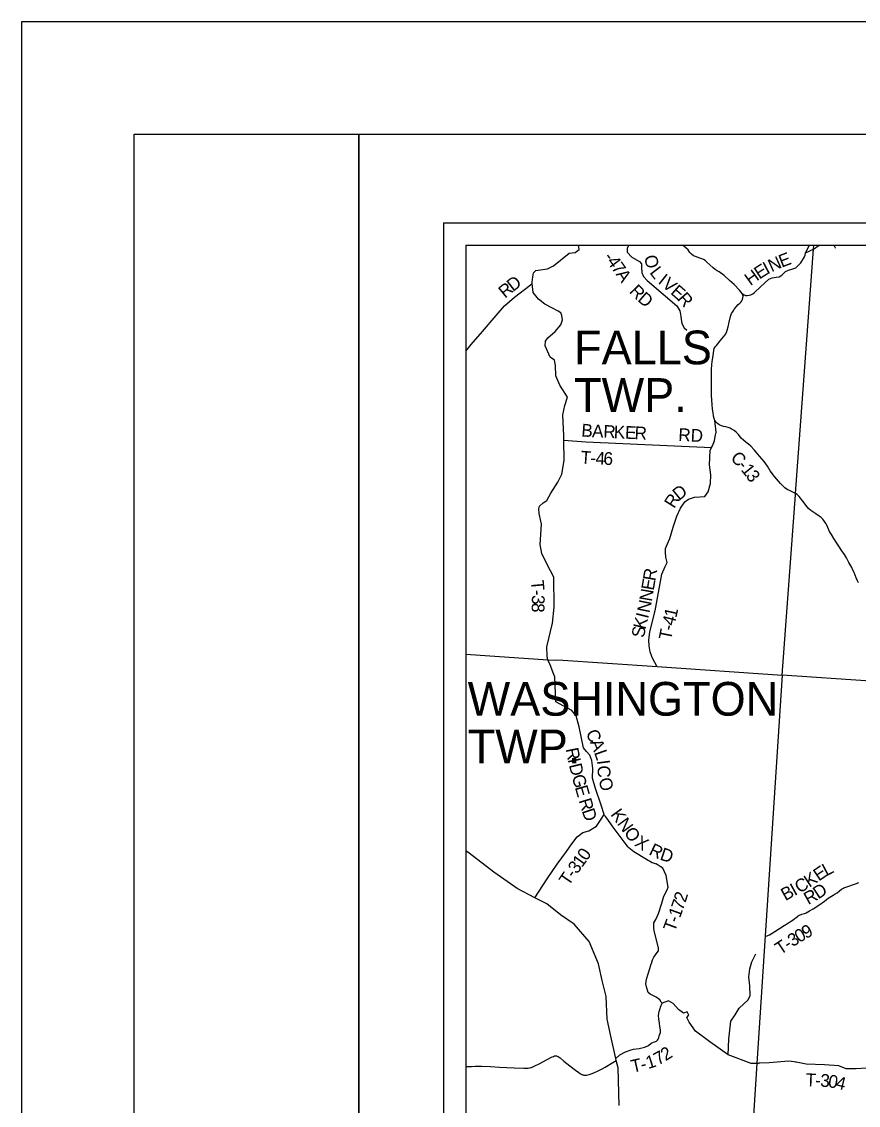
# Model space of a CAD drawing. Extents: x 0 to 34, y 0 to 22.
# Drawn here: x 0 to 3.722, y 17.181 to 22 of the extents above; entities that cross this region are included whole.
import ezdxf

# ---------------------------------------------------------------- set-up
doc = ezdxf.new("R2010")
doc.units = 0
for name, color, linetype in [('GM_X_County_Road', 7, 'Continuous'), ('GM_X_County_Road_Text', 7, 'Continuous'), ('GM_X_Township_Road', 7, 'Continuous'), ('GM_X_Township_Road_Text', 7, 'Continuous'), ('GM_X_Township_Text', 7, 'Continuous'), ('SH_Border', 7, 'Continuous'), ('SH_Cut_Line', 7, 'Continuous'), ('SH_Data', 7, 'Continuous')]:
    doc.layers.add(name, color=color, linetype=linetype)

msp = doc.modelspace()

# ---------------------------------------------------------------- linework, layer by layer
at = {"layer": 'GM_X_County_Road'}
for points in [[(3.2063, 20.7907), (3.1935, 20.8065), (3.1705, 20.8311), (3.1499, 20.8493), (3.1254, 20.8705), (3.1031, 20.888), (3.0945, 20.8927), (3.0849, 20.8984), (3.076, 20.9052), (3.0619, 20.9182), (3.0488, 20.9307), (3.0403, 20.938), (3.0331, 20.9423), (3.0256, 20.9455), (3.0172, 20.9485), (2.9974, 20.9551), (2.9897, 20.959), (2.9808, 20.9661), (2.9733, 20.974), (2.9646, 20.9848), (2.9552, 20.9937), (2.9394, 21.0054)], [(3.0837, 20.2266), (3.0811, 20.2354), (3.0786, 20.2456), (3.0761, 20.2607), (3.0739, 20.2773), (3.0716, 20.2977), (3.0702, 20.3174), (3.0696, 20.3385), (3.0697, 20.3687), (3.0692, 20.4145), (3.0697, 20.4539), (3.0708, 20.4738), (3.0727, 20.4885), (3.0753, 20.5045), (3.0776, 20.5253), (3.079, 20.5389), (3.0816, 20.5465), (3.0852, 20.5535), (3.0907, 20.5601), (3.1079, 20.58), (3.1294, 20.6079), (3.1355, 20.6175), (3.139, 20.628), (3.1428, 20.643), (3.1473, 20.6643), (3.1536, 20.689), (3.1587, 20.7021), (3.162, 20.7087), (3.168, 20.7171), (3.1721, 20.7232), (3.1885, 20.7422), (3.1952, 20.7479), (3.2008, 20.7544), (3.2041, 20.7592), (3.2075, 20.7649), (3.2089, 20.7718), (3.2094, 20.779), (3.2089, 20.7832), (3.2063, 20.7907)], [(3.443, 19.9019), (3.4342, 19.9066), (3.4164, 19.9144), (3.4089, 19.9184), (3.4019, 19.9226), (3.3959, 19.9273), (3.3888, 19.9336), (3.3765, 19.9467), (3.3667, 19.9571), (3.3499, 19.9776), (3.3308, 20.0033), (3.3177, 20.0234), (3.3029, 20.0445), (3.2833, 20.0679), (3.2675, 20.0858), (3.2593, 20.0963), (3.2438, 20.1123), (3.2342, 20.1212), (3.2239, 20.1285), (3.2122, 20.1385), (3.2014, 20.1484), (3.1887, 20.1636), (3.1784, 20.1748), (3.1702, 20.1818), (3.1615, 20.1871), (3.1524, 20.1922), (3.1437, 20.1946), (3.1329, 20.1975), (3.1226, 20.1999), (3.1137, 20.2027), (3.1069, 20.2054), (3.1018, 20.2081), (3.0957, 20.2128), (3.0915, 20.2168), (3.0837, 20.2266)], [(3.7237, 19.505), (3.719, 19.5135), (3.7135, 19.526), (3.7084, 19.5382), (3.7032, 19.5504), (3.6986, 19.5602), (3.6928, 19.5732), (3.6806, 19.595), (3.6695, 19.6155), (3.6606, 19.6301), (3.6497, 19.6471), (3.6138, 19.7011), (3.6023, 19.7187), (3.5941, 19.7334), (3.5873, 19.75), (3.5819, 19.7608), (3.5789, 19.7668), (3.5742, 19.7732), (3.5684, 19.7814), (3.5638, 19.7871), (3.5571, 19.7943), (3.5486, 19.8016), (3.5339, 19.8113), (3.5114, 19.8256), (3.5011, 19.8349), (3.4952, 19.8419), (3.4748, 19.8675), (3.4586, 19.8881), (3.4501, 19.8966), (3.443, 19.9019)], [(2.6581, 17.1799), (2.6533, 17.3472), (2.6457, 17.3805), (2.6437, 17.3894), (2.6215, 17.4892), (2.6049, 17.5635), (2.6005, 17.6656), (2.5832, 17.7362), (2.5659, 17.8105), (2.5254, 17.9102), (2.4576, 17.9863), (2.3967, 18.0286), (2.3362, 18.0777), (2.2832, 18.1036), (2.2047, 18.1459), (2.1001, 18.2173), (1.9913, 18.3019), (1.9763, 18.3122)], [(1.9763, 17.3536), (1.9803, 17.3536), (2.002, 17.354), (2.0175, 17.3548), (2.033, 17.3554), (2.0425, 17.3552), (2.0453, 17.3552), (2.0855, 17.3529), (2.1258, 17.3511), (2.191, 17.3475), (2.2344, 17.3458), (2.2469, 17.3458), (2.2532, 17.3464), (2.2594, 17.3473), (2.2655, 17.3488), (2.2685, 17.3498), (2.2743, 17.352), (2.28, 17.3547), (2.3049, 17.3675), (2.3352, 17.3834), (2.3599, 17.3963), (2.3656, 17.3987), (2.3713, 17.4005), (2.3742, 17.4009), (2.3771, 17.401), (2.38, 17.4006), (2.3828, 17.3998), (2.3855, 17.3986), (2.3907, 17.3954), (2.3956, 17.3916), (2.4124, 17.3778), (2.439, 17.3563), (2.4636, 17.3375), (2.4785, 17.3265), (2.4861, 17.3211), (2.4916, 17.3181), (2.4945, 17.3168), (2.4976, 17.3158), (2.5007, 17.3153), (2.5067, 17.3148), (2.5096, 17.3149), (2.5127, 17.3152), (2.5189, 17.3164), (2.5249, 17.318), (2.5338, 17.3211), (2.5453, 17.3259), (2.5652, 17.3349), (2.582, 17.3431), (2.5956, 17.3505), (2.6306, 17.3708), (2.6457, 17.3805)]]:
    msp.add_lwpolyline(points, dxfattribs=at)
at = {"layer": 'GM_X_Township_Road'}
for points in [[(1.9763, 20.5346), (2.0003, 20.5641), (2.0498, 20.6217), (2.1114, 20.6937), (2.1479, 20.7357), (2.1931, 20.7752), (2.2623, 20.8286), (2.271, 20.8361), (2.2714, 20.8415), (2.2737, 20.8646), (2.2772, 20.8824), (2.2882, 20.8934), (2.339, 20.9006), (2.366, 20.9138), (2.4363, 20.9699), (2.4625, 20.9736), (2.48, 20.9873), (2.4774, 21.0054)], [(2.7005, 21.0054), (2.7, 21.0049), (2.6939, 20.9909), (2.6946, 20.9753), (2.7147, 20.9521), (2.7488, 20.9339), (2.7575, 20.9225), (2.7579, 20.9164), (2.7578, 20.9062), (2.7589, 20.8853), (2.7661, 20.8671), (2.7835, 20.8489), (2.9153, 20.7357), (2.9285, 20.7137), (2.9308, 20.6993)], [(3.2063, 20.7907), (3.2138, 20.7846), (3.2211, 20.7828), (3.2279, 20.7821), (3.2361, 20.7834), (3.2439, 20.7851), (3.2532, 20.7898), (3.2603, 20.7949), (3.2864, 20.821), (3.3241, 20.8555), (3.3396, 20.8612), (3.3575, 20.8631), (3.37, 20.8657), (3.3825, 20.8733), (3.3981, 20.8888), (3.4118, 20.8952), (3.4315, 20.9005), (3.4448, 20.9058), (3.4661, 20.927), (3.4832, 20.954), (3.4863, 20.9623), (3.487, 20.9727), (3.5047, 21.0054)], [(3.487, 20.9727), (3.5229, 20.9876), (3.5477, 21.0054)], [(3.6148, 21.0024), (3.6172, 20.9981), (3.6191, 20.9931)], [(2.3679, 19.0967), (2.3508, 19.1396), (2.3414, 19.1616), (2.3385, 19.1788), (2.3371, 19.2202), (2.3613, 19.325), (2.3692, 19.3959), (2.3672, 19.5303), (2.338, 19.5856), (2.3141, 19.6353), (2.3072, 19.6744), (2.3133, 19.7658), (2.3026, 19.8125), (2.3003, 19.8338), (2.3034, 19.8448), (2.3204, 19.86), (2.336, 19.8702), (2.3546, 19.9037), (2.3849, 19.9515), (2.4027, 19.988), (2.413, 20.0487), (2.4126, 20.1382), (2.4125, 20.158), (2.4083, 20.2517), (2.4163, 20.2924), (2.4292, 20.3299), (2.3938, 20.3842), (2.3768, 20.4255), (2.3752, 20.4714), (2.3706, 20.4942), (2.3513, 20.5086), (2.3284, 20.5591), (2.3303, 20.5796), (2.3407, 20.5944), (2.3733, 20.6225), (2.3988, 20.6516), (2.406, 20.6738), (2.4035, 20.693), (2.3984, 20.7045), (2.3876, 20.7127), (2.3595, 20.7268), (2.3269, 20.7443), (2.2996, 20.7659), (2.2755, 20.7963), (2.271, 20.8361)], [(2.9308, 20.6993), (2.9326, 20.6879), (2.934, 20.6766), (2.9364, 20.6583), (2.9473, 20.6378), (2.9594, 20.6281)], [(2.8036, 19.1772), (2.7961, 19.1971), (2.7921, 19.2244), (2.7904, 19.2495), (2.795, 19.2859), (2.8189, 19.3793), (2.8477, 19.5423), (2.8637, 19.5777), (2.8646, 19.5796), (2.8713, 19.5946), (2.8665, 19.6182), (2.8648, 19.6403), (2.8652, 19.6573), (2.8729, 19.6777), (2.8833, 19.701), (2.8993, 19.7519), (2.9145, 19.8017), (2.9305, 19.837), (2.9501, 19.8643), (2.9675, 19.8768), (2.9942, 19.8849), (3.0395, 19.8888), (3.0544, 19.9086), (3.0644, 19.9467), (3.0668, 19.985), (3.0606, 20.0288), (3.0629, 20.0933), (3.0696, 20.1066), (3.0736, 20.1143), (3.0828, 20.1354), (3.0848, 20.1551), (3.09, 20.1739), (3.0837, 20.2266)], [(2.4126, 20.1382), (2.5098, 20.1315), (3.0696, 20.1066)], [(2.8278, 19.1316), (2.8064, 19.1698), (2.8036, 19.1772)], [(2.591, 18.4737), (2.5779, 18.5158), (2.5528, 18.5894), (2.5403, 18.6365), (2.5407, 18.6782), (2.5368, 18.7146), (2.5273, 18.7378), (2.5133, 18.7537), (2.5, 18.7704), (2.481, 18.8648), (2.4666, 18.913), (2.4476, 18.9361), (2.3762, 18.9755), (2.3747, 19.0127), (2.3719, 19.0867), (2.3679, 19.0967)], [(2.2832, 18.1036), (2.3382, 18.1876), (2.3829, 18.2541), (2.4239, 18.3092), (2.4482, 18.3445), (2.4709, 18.3753), (2.4965, 18.3935), (2.5232, 18.4012), (2.5578, 18.4225), (2.5752, 18.4494), (2.591, 18.4737), (2.5967, 18.4652)], [(2.5967, 18.4652), (2.6058, 18.4515), (2.6256, 18.4244), (2.6787, 18.3527), (2.6943, 18.3329), (2.7229, 18.3098), (2.7796, 18.2755), (2.8048, 18.2609), (2.8227, 18.2548)], [(2.8016, 17.8121), (2.8059, 17.8274), (2.812, 17.8396), (2.8275, 17.8601), (2.8332, 17.8681), (2.8336, 17.8806), (2.816, 17.9511), (2.8119, 17.9675), (2.8131, 17.9918), (2.8214, 18.0073), (2.8328, 18.0339), (2.8476, 18.0806), (2.8566, 18.1117), (2.8718, 18.1395), (2.876, 18.1505), (2.8669, 18.2032), (2.8525, 18.2355), (2.8407, 18.2433), (2.8227, 18.2548)], [(3.3142, 17.9331), (3.3229, 17.9371), (3.3268, 17.9392), (3.3511, 17.9544), (3.3717, 17.9673), (3.392, 17.9806), (3.411, 17.9931), (3.4248, 18.002), (3.4363, 18.0095), (3.4417, 18.0131), (3.4464, 18.0166), (3.4511, 18.0208), (3.4554, 18.0241), (3.4599, 18.0268), (3.4639, 18.0288), (3.4674, 18.0301), (3.4708, 18.0312), (3.4769, 18.0327), (3.4825, 18.0339), (3.4871, 18.0354), (3.4901, 18.0371), (3.5053, 18.0455), (3.5215, 18.0551), (3.5553, 18.077), (3.563, 18.0822), (3.5702, 18.0877), (3.5806, 18.0968), (3.5877, 18.102), (3.5957, 18.1068), (3.6106, 18.1157), (3.6198, 18.1208), (3.6281, 18.1266), (3.6383, 18.1346), (3.6471, 18.1416), (3.6527, 18.1454), (3.6582, 18.1481), (3.6668, 18.1511), (3.7136, 18.1681), (3.7209, 18.1709), (3.725, 18.1725)], [(3.1427, 17.4048), (3.1462, 17.4745), (3.155, 17.5555), (3.1738, 17.584), (3.192, 17.6128), (3.2323, 17.6495), (3.2419, 17.6698), (3.2398, 17.7119), (3.2347, 17.7519), (3.2394, 17.7873), (3.248, 17.8197), (3.266, 17.8553)], [(2.8312, 17.4747), (2.8341, 17.4814), (2.8356, 17.4905), (2.8425, 17.5049), (2.8428, 17.5163), (2.8394, 17.5311), (2.8371, 17.547), (2.8352, 17.5649), (2.8333, 17.5801), (2.836, 17.5979), (2.8402, 17.6112), (2.8424, 17.6176), (2.8501, 17.6346), (2.8455, 17.64), (2.8394, 17.6503), (2.8223, 17.6624), (2.8139, 17.6662), (2.8048, 17.6703), (2.7965, 17.6752), (2.787, 17.6828), (2.7794, 17.7082), (2.7771, 17.7215), (2.7798, 17.742), (2.7949, 17.7887), (2.801, 17.8101), (2.8016, 17.8121)], [(3.1427, 17.4048), (3.0613, 17.4636), (2.9975, 17.5106), (2.9692, 17.5503), (2.9591, 17.5722), (2.9677, 17.5826), (2.9615, 17.5968), (2.9443, 17.5911), (2.9227, 17.6075), (2.8983, 17.6339), (2.8777, 17.6454), (2.8501, 17.6346)], [(2.6437, 17.3894), (2.6611, 17.4052), (2.6858, 17.4182), (2.7115, 17.4272), (2.7214, 17.4307), (2.7476, 17.4334), (2.773, 17.4392), (2.789, 17.4468), (2.8004, 17.4578), (2.8117, 17.4624), (2.8239, 17.4666), (2.8292, 17.47), (2.8312, 17.4747)], [(3.2796, 17.3678), (3.2766, 17.3673), (3.2716, 17.3665), (3.2451, 17.3667), (3.1427, 17.4048)], [(3.4432, 17.3733), (3.4373, 17.3741), (3.4126, 17.3775), (3.3255, 17.3696), (3.2845, 17.3686), (3.2796, 17.3678)], [(3.7885, 17.3464), (3.7868, 17.346), (3.7855, 17.346), (3.7823, 17.346), (3.7637, 17.3459), (3.759, 17.3461), (3.7128, 17.3428), (3.668, 17.343), (3.6353, 17.357), (3.572, 17.3611), (3.4909, 17.3644), (3.4452, 17.373), (3.4432, 17.3733)]]:
    msp.add_lwpolyline(points, dxfattribs=at)
at = {"layer": 'GM_X_Township_Text'}
for points in [[(1.9763, 19.187), (2.3412, 19.1621), (2.3735, 19.1599), (2.3853, 19.1626), (2.8276, 19.1321), (3.3833, 19.0938), (3.4423, 19.896), (3.4428, 19.9024), (3.5227, 20.9882), (3.524, 21.0054)], [(8.7763, 18.7365), (7.7116, 18.8006), (7.6851, 18.802), (7.2653, 18.8305), (6.9608, 18.8511), (6.9477, 18.852), (6.9018, 18.8551), (6.7713, 18.864), (6.3469, 18.8928), (5.4766, 18.9518), (4.3125, 19.0308), (4.2973, 19.0318), (4.1694, 19.0405), (3.3833, 19.0938), (3.2714, 17.3671), (3.2279, 16.6952), (3.1822, 15.9898), (3.1607, 15.6594), (3.1102, 14.8789), (3.0682, 14.2309), (3.0665, 14.2054)]]:
    msp.add_lwpolyline(points, dxfattribs=at)
at = {"layer": 'SH_Border'}
for points in [[(0.5, 21.5), (1.5, 21.5), (1.5, 0.5), (0.5, 0.5)], [(1.5, 21.5), (33.5, 21.5), (33.5, 0.5), (1.5, 0.5)]]:
    msp.add_lwpolyline(points, close=True, dxfattribs=at)
at = {"layer": 'SH_Cut_Line'}
msp.add_lwpolyline([(0, 0), (34, 0), (34, 22), (0, 22)], close=True, dxfattribs=at)
at = {"layer": 'SH_Data'}
for p, q in [((1.8763, 21.1054), (8.8763, 21.1054)), ((1.8763, 21.1054), (1.8763, 14.1054)), ((1.9763, 21.0054), (1.9763, 14.2054)), ((1.9763, 21.0054), (8.7763, 21.0054))]:
    msp.add_line(p, q, dxfattribs=at)

# ---------------------------------------------------------------- texts
at = {"layer": 'GM_X_County_Road_Text'}
for s, rotation, p in [('C', 315.0386, (3.1505, 20.0558)), ('-', 311.0839, (3.1828, 20.0236)), ('1', 308.6354, (3.1978, 20.0065)), ('3', 306.9074, (3.2193, 19.9795))]:
    msp.add_text(s, height=0.0568, rotation=rotation, dxfattribs=at).set_placement(p)
at = {"layer": 'GM_X_Township_Road_Text'}
for s, height, rotation, p in [('-', 0.0568, 307.7114, (2.5869, 20.9511)), ('E', 0.0568, 20.9824, (3.3813, 20.9056)), ('4', 0.0568, 306.3381, (2.6009, 20.933)), ('7', 0.0568, 305.044, (2.6215, 20.905)), ('O', 0.0568, 284.349, (2.7681, 20.9547)), ('E', 0.0568, 32.814, (3.2821, 20.8525)), ('I', 0.0568, 27.7869, (3.3166, 20.8749)), ('N', 0.0568, 24.2414, (3.3365, 20.8854)), ('A', 0.0568, 304.0558, (2.6414, 20.8766)), ('L', 0.0568, 307.3732, (2.7913, 20.884)), ('I', 0.0568, 321.5904, (2.8279, 20.8392)), ('V', 0.0568, 319.2774, (2.8457, 20.8251)), ('H', 0.0568, 35.7435, (3.2421, 20.8238)), ('R', 0.0568, 39.6826, (2.1504, 20.7677)), ('D', 0.0568, 37.9191, (2.186, 20.7972)), ('R', 0.0568, 313.9788, (2.7005, 20.7979)), ('E', 0.0568, 318.7907, (2.8835, 20.7926)), ('D', 0.0568, 319.3579, (2.7371, 20.7604)), ('R', 0.0568, 311.1389, (2.914, 20.766)), ('B', 0.0568, 355.8515, (2.4886, 20.1557)), ('A', 0.0568, 357.3954, (2.5369, 20.1522)), ('R', 0.0568, 357.4516, (2.5869, 20.1499)), ('K', 0.0568, 357.4457, (2.6335, 20.1478)), ('E', 0.0568, 357.4499, (2.6834, 20.1456)), ('R', 0.0568, 357.4467, (2.7259, 20.1437)), ('RD', 0.05682, 357.0406, (2.9204, 20.1358)), ('T', 0.0568, 355.9638, (2.4853, 20.0354)), ('-', 0.0568, 357.4043, (2.5293, 20.0323)), ('4', 0.0568, 357.5766, (2.5528, 20.0313)), ('6', 0.0568, 357.6525, (2.5878, 20.0298)), ('D', 0.0568, 39.0313, (2.9246, 19.8679)), ('R', 0.0568, 58.0248, (2.9032, 19.832)), ('R', 0.0568, 80.2816, (2.819, 19.5102)), ('T', 0.0568, 275.2014, (2.2659, 19.5144)), ('E', 0.0568, 80.2856, (2.8119, 19.4683)), ('-', 0.0568, 270.7338, (2.2697, 19.4733)), ('N', 0.0568, 80.2095, (2.8033, 19.419)), ('3', 0.0568, 270.4684, (2.27, 19.45)), ('N', 0.0568, 78.5419, (2.7931, 19.3682)), ('8', 0.0568, 267.3764, (2.2703, 19.4158)), ('1', 0.0568, 77.6475, (2.9125, 19.3464)), ('K', 0.0568, 76.1917, (2.7748, 19.2943)), ('I', 0.0568, 75.9013, (2.7868, 19.3428)), ('4', 0.0568, 75.6547, (2.9033, 19.3104)), ('S', 0.0568, 81.5594, (2.7695, 19.2578)), ('T', 0.0568, 78.6985, (2.8894, 19.2469)), ('-', 0.0568, 75.5946, (2.8975, 19.2877)), ('C', 0.0568, 292.7712, (2.509, 18.8388)), ('A', 0.0568, 292.6294, (2.5271, 18.7958)), ('R', 0.0568, 281.2181, (2.4199, 18.7657)), ('L', 0.0568, 288.9256, (2.546, 18.7505)), ('I', 0.0568, 282.0259, (2.4292, 18.7191)), ('D', 0.0568, 283.7249, (2.4344, 18.6945)), ('I', 0.0568, 277.4368, (2.5591, 18.7133)), ('G', 0.0568, 285.7732, (2.4469, 18.6438)), ('C', 0.0568, 271.4755, (2.562, 18.6917)), ('E', 0.0568, 286.1901, (2.4606, 18.5952)), ('O', 0.0568, 285.7139, (2.5655, 18.6298)), ('R', 0.0568, 286.9189, (2.4776, 18.5369)), ('D', 0.0568, 288.1467, (2.4916, 18.4909)), ('K', 0.0568, 305.9395, (2.6177, 18.4742)), ('N', 0.0568, 306.0321, (2.6471, 18.4337)), ('O', 0.0568, 307.058, (2.6771, 18.3924)), ('X', 0.0568, 327.2475, (2.7232, 18.3377)), ('0', 0.0568, 55.0391, (2.5135, 18.2649)), ('R', 0.0568, 334.154, (2.7868, 18.298)), ('D', 0.0568, 341.4359, (2.8361, 18.2747)), ('3', 0.0568, 53.0031, (2.4706, 18.2068)), ('1', 0.0568, 53.9687, (2.4922, 18.2356)), ('T', 0.0568, 55.8369, (2.4336, 18.1533)), ('-', 0.0568, 54.5041, (2.4572, 18.1881)), ('K', 0.0568, 33.709, (3.5044, 18.1478)), ('E', 0.0568, 34.2134, (3.5465, 18.1758)), ('L', 0.0568, 28.018, (3.5802, 18.1989)), ('I', 0.0568, 28.765, (3.4385, 18.1113)), ('C', 0.0568, 28.7988, (3.459, 18.1225)), ('2', 0.0568, 72.9983, (2.9536, 18.0801)), ('B', 0.0568, 28.765, (3.3976, 18.0888)), ('R', 0.0568, 29.0269, (3.4995, 18.0709)), ('D', 0.0568, 33.3048, (3.5442, 18.0959)), ('7', 0.0568, 70.4882, (2.9411, 18.0445)), ('1', 0.0568, 69.7039, (2.9286, 18.0109)), ('T', 0.0568, 69.5453, (2.9056, 17.949)), ('-', 0.0568, 69.5553, (2.9204, 17.9888)), ('9', 0.0568, 28.483, (3.489, 17.9199)), ('3', 0.0568, 32.2293, (3.4301, 17.8839)), ('0', 0.0568, 30.6505, (3.4594, 17.9024)), ('T', 0.0568, 33.532, (3.3755, 17.8479)), ('-', 0.0568, 33.1986, (3.4108, 17.8713)), ('1', 0.0568, 17.9414, (2.7872, 17.3417)), ('7', 0.0568, 29.6979, (2.8321, 17.3576)), ('2', 0.0568, 32.0057, (2.8647, 17.3763)), ('T', 0.0568, 12.7659, (2.7177, 17.3255)), ('-', 0.0568, 13.2923, (2.7597, 17.335)), ('T', 0.0568, 357.6343, (3.4869, 17.2668)), ('3', 0.0568, 356.9485, (3.5522, 17.264)), ('0', 0.0568, 351.2378, (3.5854, 17.2623)), ('4', 0.0568, 346.4242, (3.6185, 17.2573)), ('-', 0.0568, 357.4916, (3.5292, 17.265))]:
    msp.add_text(s, height=height, rotation=rotation, dxfattribs=at).set_placement(p)
at = {"layer": 'GM_X_Township_Text'}
for s, p in [('FALLS', (2.4577, 20.4763)), ('TWP.', (2.4577, 20.2647)), ('WASHINGTON', (1.9843, 18.9137)), ('TWP.', (1.9843, 18.7021))]:
    msp.add_text(s, height=0.15, rotation=0, dxfattribs=at).set_placement(p)

doc.saveas('drawing.dxf')
